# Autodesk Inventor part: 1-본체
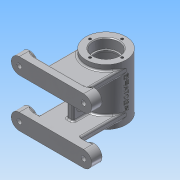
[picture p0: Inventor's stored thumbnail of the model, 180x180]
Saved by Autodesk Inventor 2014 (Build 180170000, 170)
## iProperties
Created: 2015-11
Part Number: 1-본체
Material: 알루미늄 6061
Document SubType Name: Modeling
Designer: 103-17
Density: 2.71 g/cm^3
Appearance: 알루미늄 - 평지
Mass: 359.139 g
Surface Area: 459.815 cm^2
Volume: 132.523 cm^3
Author: 103-17
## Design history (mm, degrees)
sketch "스케치1"
  geometry: C1 r 25 at (0, 0); 1 further point
  constraints: 1 centre point, 1 coincident
  dimensions: "d0" = 50 diameter of C1
extrude "돌출1" new body sketch "스케치1" stored distance "d1" = 70; taper "d2" = 0 deg
node "작업 평면1"
sketch "스케치2"
  geometry: L1 (-25, -35)-(25, -35) reference; L2 (25, 35)-(-25, 35) reference; L3 (-40, 40)-(40, 40); L4 (40, 20)-(-40, 20); L5 (-40, -20)-(40, -20); L6 (-40, -40)-(40, -40); A1 r 10 centre (-40, 30) between (-40, 40) and (-40, 20); A2 r 10 centre (40, 30) between (40, 40) and (40, 20); A3 r 10 centre (-40, -30) between (-40, -20) and (-40, -40); A4 r 10 centre (40, -30) between (40, -20) and (40, -40); 1 further point
  constraints: 8 end point, 8 point on circle, 5 tangent, 4 centre point, 3 equal radius, 2 horizontal, 2 horizontal alignment, 2 vertical alignment, 1 parallel
  dimensions: "d4" = 20 diameter of A1; "d5" = 80 distance of A2.centre A1.centre; "d6" = 40 horizontal distance of A1.centre point (0, 0); "d15" = 80 distance of L6.end L3.end; "d16" = 40 horizontal distance of L3.start point (0, 0)
  node "투영된 루프1"
extrude "돌출2" join sketch "스케치2" distance "d9" = 10; taper "d10" = 0 deg
extrude "돌출3" join sketch "스케치2" distance "d11" = 13; taper "d12" = 0 deg
sketch "스케치3"
  geometry: L1 (40, -20)-(-40, -20) reference; L2 (-40, 40)-(40, 40) reference; L3 (40, 20)-(-40, 20) reference; L4 (-25, 20)-(-25, 28); L5 (-25, 28)-(25, 28); L6 (25, 28)-(25, 20); L7 (-25, -20)-(-25, -28); L8 (-25, -28)-(25, -28); L9 (25, -28)-(25, -20); A1 r 10 centre (40, 30) between (40, 20) and (40, 40) reference; A2 r 10 centre (-40, 30) between (-40, 40) and (-40, 20) reference; 3 further points
  constraints: 12 end point, 5 perpendicular, 4 point on line, 2 equal length, 2 midpoint, 2 vertical alignment, 1 parallel
  dimensions: "d13" = 8 distance of L5.end L6.end; "d14" = 50 distance of L4.end L5.end
extrude "돌출4" join sketch "스케치3" stored distance "d17" = 13; taper "d18" = 0 deg
node "작업 평면2"
sketch "스케치4"
  geometry: L1 (25, -28)-(-25, -28) reference; L2 (-25, -28)-(-25, -20) reference; L3 (-25, -20)-(25, -20) reference; L4 (25, -20)-(25, -28) reference; L5 (-25, 28)-(25, 28) reference; L6 (25, 28)-(25, 20) reference; L7 (25, 20)-(-25, 20) reference; L8 (-25, 20)-(-25, 28) reference; L9 (-4, 20)-(-4, -20); L10 (4, 20)-(4, -20); 1 further point
  constraints: 4 end point, 4 point on line, 2 perpendicular
  dimensions: "d20" = 8 distance between parallel lines of L9 L10; "d21" = 4 distance from line of point (0, 0) L9
extrude "돌출5" join sketch "스케치4" stored distance "d22" = 8; taper "d23" = 0 deg
sketch "스케치5"
  geometry: L1 (0, 20.322)-(40, 20.322) reference; L2 (40, 20.322)-(40, 0) reference; L3 (12, 13.5)-(28, 13.5); L4 (28, 6.5)-(12, 6.5); L5 (40, -23)-(60, -23) reference; A1 r 3.5 centre (28, 10) between (28, 6.5) and (28, 13.5); A2 r 3.5 centre (12, 10) between (12, 13.5) and (12, 6.5); 3 further points
  constraints: 4 end point, 4 point on circle, 4 tangent, 2 centre point, 2 midpoint, 1 parallel, 1 perpendicular, 1 vertical alignment
  dimensions: "d24" = 23 dimension on A1 A2; "d25" = 3.5 radius of A1; "d26" = 33 distance from line of L5 A1.centre
extrude "돌출6" cut sketch "스케치5" stored distance "d27" = 0; taper "d28" = 0 deg
sketch "스케치6"
  geometry: C1 r 10 at (0, 0) reference; C2 r 10 at (0, -60) reference; C3 r 10 at (-80, -60) reference; C4 r 10 at (-80, 0) reference; 5 further points
  constraints: 4 coincident
hole "구멍1" sketch "스케치6" at (-80, 0), (0, 0), (0, -60), (-80, -60) diameter "d29" = 6; stored, may be unused: countersink angle "d33" = 90 deg, drill point angle "d35" = 118 deg; dims "d30" = 6, "d31" = 12, "d32" = 4, "d34" = 8
hole "구멍2" diameter "d38" = 28; stored, may be unused: countersink angle "d42" = 90 deg, drill point angle "d44" = 0 deg; dims "d39" = 6, "d40" = 32, "d41" = 12, "d43" = 14, "d45" = 10, "d46" = 10
hole "구멍3" diameter "d49" = 42; stored, may be unused: countersink angle "d53" = 90 deg, drill point angle "d55" = 0 deg; dims "d47" = 10, "d48" = 10, "d50" = 6, "d51" = 32, "d52" = 12, "d54" = 42
sketch "스케치7"
  geometry: C1 r 16 at (0, 0) reference; 1 further point
  constraints: 1 vertical alignment
  dimensions: "d56" = 20 distance of point (0, 20) C1.centre
hole "구멍4" sketch "스케치7" at (0, 20) diameter "d57" = 3.242; stored, may be unused: countersink angle "d61" = 90 deg, drill point angle "d63" = 118 deg; dims "d58" = 8, "d59" = 32, "d60" = 12, "d62" = 10
node "작업 평면3"
sketch "스케치8"
  geometry: C1 r 5 at (0, 0); 1 further point
  constraints: 1 centre point, 1 coincident
  dimensions: "d68" = 10 diameter of C1
extrude "돌출7" join sketch "스케치8" stored distance "d69" = 8; taper "d70" = 0 deg
node "작업 평면5"
  node "작업 평면4"
sketch "스케치9"
  geometry: C1 r 6 at (0, 0); 1 further point
  constraints: 1 centre point, 1 coincident
  dimensions: "d73" = 12 diameter of C1
extrude "돌출8" join sketch "스케치9" stored distance "d74" = 8; taper "d75" = 0 deg
hole "구멍5" diameter "d78" = 5.188; stored, may be unused: countersink angle "d82" = 90 deg, drill point angle "d84" = 118 deg; dims "d76" = 10, "d77" = 10, "d79" = 8, "d80" = 32, "d81" = 12, "d83" = 10
hole "구멍6" diameter "d87" = 5.188; stored, may be unused: countersink angle "d91" = 90 deg, drill point angle "d93" = 0 deg; dims "d85" = 10, "d86" = 10, "d88" = 8, "d89" = 32, "d90" = 12, "d92" = 10
node "작업 평면6"
sketch "스케치10"
  geometry: L1 (25, -35)-(25, 35) reference; L2 (25, 35)-(-25, 35) reference; 2 further points
  constraints: 1 other
  dimensions: "d95" = 35 distance from line of L2 point (0, 0); "d96" = 25 distance from line of L1 point (0, 0)
feature "엠보싱1" sketch "스케치10" dims "d1" = 70, "d97" = 0.5, "d98" = 0
fillet "모깎기1" dims "d99" = 3, "d100" = 0.3, "d101" = 2
fillet "모깎기2" dims "d102" = 2
fillet "모깎기3" dims "d103" = 2
fillet "모깎기4" dims "d104" = 2
chamfer "모따기1" distance "d105" = 1; stored, may be unused: second distance "d106" = 2, angle "d107" = 45 deg
node "솔리드1"
mirror "대칭1"
pattern_circular "원형 패턴1" dims angle "d65" = 360 deg
mirror "대칭2"
node "투영된 루프2"
node "투영된 루프3"
node "투영된 루프4"
node "투영된 루프5"
node "절단 모서리 투영1"
other parameters: "d3" = -68, "d19" = -45, "d67" = 28, "d71" = 30 deg, "d72" = -28, "d94" = 49.25
